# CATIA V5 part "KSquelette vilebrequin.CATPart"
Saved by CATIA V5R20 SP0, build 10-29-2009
Part number: K_Squelette vilebrequin
Bounding box of the stored display mesh (mm): x -50 to 50, y 90 to 125.927, z 190 to 231.307
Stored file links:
  C:\Users\thinkmotion1\Desktop\Khaled_IAO_Pack2\IAO_2010_1392_rragonneau\CATIA_1392_rragonneau\KSquelette vilebrequin.CATPart
  D:\Documents\Scolaire\MM2\IAO\Squelette\Product1.CATProduct
  C:\Users\thinkmotion1\Desktop\Khaled_IAO_Pack2\IAO_2010_1392_rragonneau\CATIA_1392_rragonneau\KSquelette bati.CATPart
  C:\Users\thinkmotion1\Desktop\Khaled_IAO_Pack2\IAO_2010_1392_rragonneau\CATIA_1392_rragonneau\KSquelette de base.CATPart
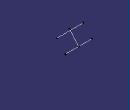
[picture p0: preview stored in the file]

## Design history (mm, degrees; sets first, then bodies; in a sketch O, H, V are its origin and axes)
External parameters (linked from other documents)
  External.diametre_vilebrequin = 100 mm
Set1
  Line1: type PtPt, FirstPoint DatumPoint1, SecondPoint DatumPoint2
  Line2: type PtPt, FirstPoint Point2, SecondPoint Point1
  Line3: type PtDir, RefPoint Point3, Direction Line2, Start 0, End 50 {= External.diametre_vilebrequin /2}
  Line4: type Normal, RefPoint vertex of Line3, RefSkin Plane1, Start -50, End 50
Set2
  DatumPoint1: linked copy from another document
  DatumPoint2: linked copy from another document
  Plane1: linked copy from another document
  Point1 to Point3: linked copy from another document
Body1 (main body)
